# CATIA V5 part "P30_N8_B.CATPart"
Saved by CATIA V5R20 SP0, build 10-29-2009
Part number: P30_N8_B
Nomenclature: P30_N8_B
Source: Unknown
Bounding box of the stored display mesh (mm): x -15 to 15, y -15 to 15, z 0 to 654
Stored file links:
  C:\Users\halimelbaba\Documents\cmv\final\P30_N8_B.CATPart
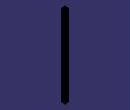
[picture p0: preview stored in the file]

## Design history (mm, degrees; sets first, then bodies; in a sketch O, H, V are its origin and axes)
Body1 "MANIFOLD_SOLID_BREP #6353" (main body)
  Solid1: solid without history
